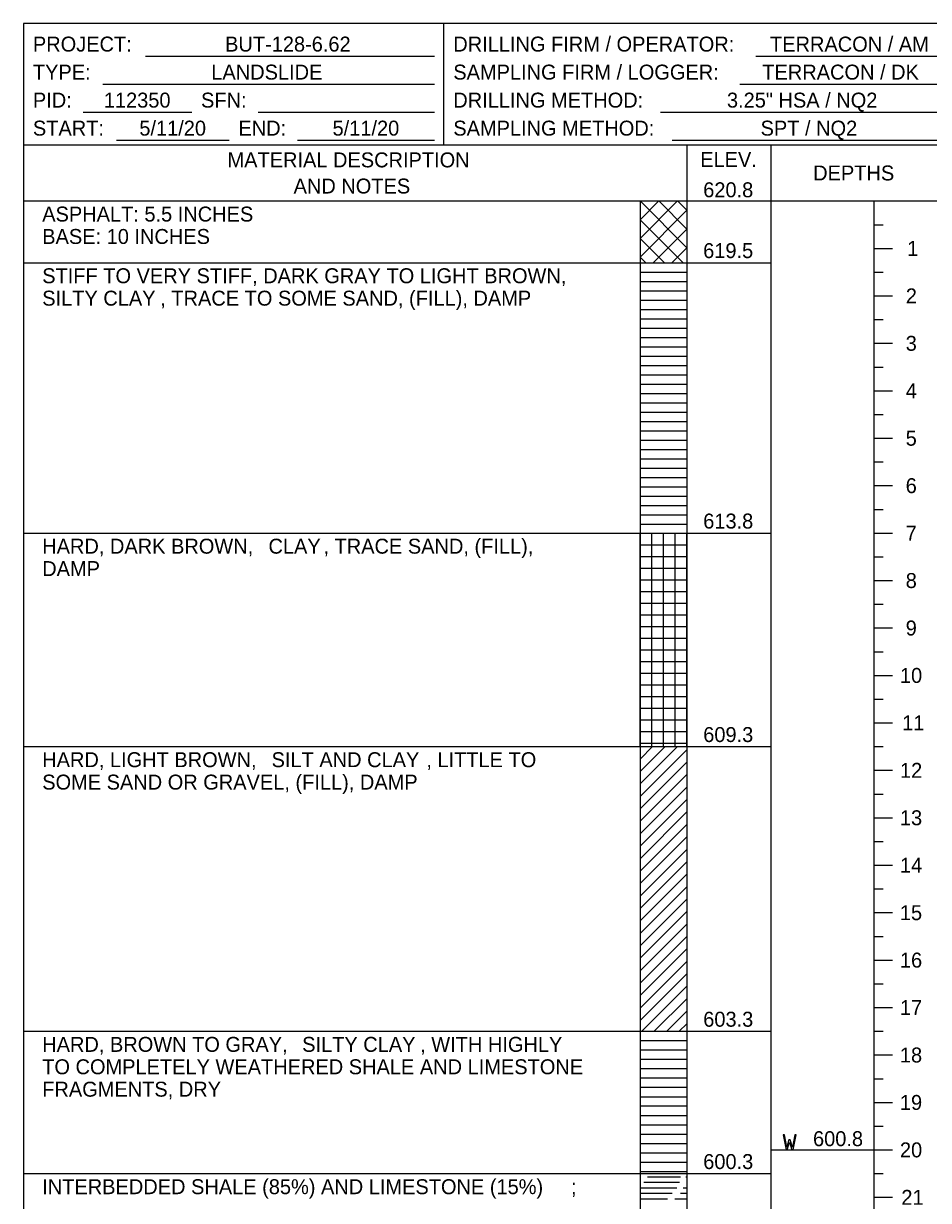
# Model space of a CAD drawing. Extents: x 0 to 0.833, y -0.323 to 0.608.
# Drawn here: x 0 to 0.404, y 0.083 to 0.608 of the extents above; entities that cross this region are included whole.
import ezdxf

# ---------------------------------------------------------------- set-up
doc = ezdxf.new("R2010")
doc.units = 0

# ---------------------------------------------------------------- blocks, each defined once
blk = doc.blocks.new('DGRFC!OHDOT FREE WATER')
blk.add_lwpolyline([(-0.00161, 0), (-0.00102, 0), (0, 0.00346), (0.00102, 0), (0.00161, 0), (0.00292, 0.00667), (0.00233, 0.00667), (0.00126, 0.00118), (0.00029, 0.00444), (-0.00029, 0.00444), (-0.00126, 0.00118), (-0.00233, 0.00667), (-0.00292, 0.00667)], close=True)

msp = doc.modelspace()

# ---------------------------------------------------------------- linework, layer by layer
msp.add_lwpolyline([(0, -0.32328), (0.83333, -0.32328), (0.83333, 0.60833), (0, 0.60833)], close=True)
for points in [[(0.1875, 0.55417), (0.1875, 0.60833)], [(0.05444, 0.59375), (0.18333, 0.59375)], [(0.32667, 0.59375), (0.4125, 0.59375)], [(0.03542, 0.58125), (0.18333, 0.58125)], [(0.31944, 0.58125), (0.4125, 0.58125)], [(0.02653, 0.56875), (0.075, 0.56875)], [(0.10458, 0.56875), (0.18333, 0.56875)], [(0.28403, 0.56875), (0.4125, 0.56875)], [(0, 0.55417), (0.83333, 0.55417)], [(0, 0.55417), (0.83333, 0.55417)], [(0, 0.55417), (0.83333, 0.55417)], [(0, 0.55417), (0.83333, 0.55417)], [(0, 0.55417), (0.83333, 0.55417)], [(0.04153, 0.55625), (0.09167, 0.55625)], [(0.12222, 0.55625), (0.18333, 0.55625)], [(0.2893, 0.55625), (0.4125, 0.55625)], [(0.29583, 0.55417), (0.29583, -0.28575)], [(0.29583, 0.55417), (0.29583, -0.28575)], [(0.33333, 0.55417), (0.33333, -0.28575)], [(0.33333, 0.55417), (0.33333, -0.28575)], [(0, 0.52917), (0.83333, 0.52917)], [(0, 0.52917), (0.83333, 0.52917)], [(0, 0.52917), (0.83333, 0.52917)], [(0, 0.52917), (0.83333, 0.52917)], [(0, 0.52917), (0.83333, 0.52917)], [(0.275, 0.52917), (0.29583, 0.50833)], [(0.275, 0.52083), (0.28333, 0.52917)], [(0.275, 0.5125), (0.29167, 0.52917)], [(0.275, 0.52917), (0.275, 0.50165)], [(0.275, 0.52917), (0.275, -0.28575)], [(0.28333, 0.52917), (0.29583, 0.51667)], [(0.29167, 0.52917), (0.29583, 0.525)], [(0.29583, 0.52917), (0.33333, 0.52917)], [(0.37917, 0.52917), (0.37917, -0.28575)], [(0.275, 0.50417), (0.29583, 0.525)], [(0.275, 0.52083), (0.29418, 0.50165)], [(0.28082, 0.50165), (0.29583, 0.51667)], [(0.37917, 0.51858), (0.38333, 0.51858)], [(0.275, 0.5125), (0.28585, 0.50165)], [(0.275, 0.50417), (0.27752, 0.50165)], [(0.28915, 0.50165), (0.29583, 0.50833)], [(0.37917, 0.508), (0.3875, 0.508)], [(0.37917, 0.508), (0.38333, 0.508)], [(0, 0.50165), (0.275, 0.50165)], [(0.275, 0.50165), (0.29583, 0.50165)], [(0.275, 0.50165), (0.29583, 0.50165)], [(0.275, 0.50165), (0.275, 0.381)], [(0.29583, 0.50165), (0.33333, 0.50165)], [(0.275, 0.49748), (0.29583, 0.49748)], [(0.37917, 0.49742), (0.38333, 0.49742)], [(0.275, 0.49332), (0.29583, 0.49332)], [(0.275, 0.48915), (0.29583, 0.48915)], [(0.275, 0.48498), (0.29583, 0.48498)], [(0.37917, 0.48683), (0.3875, 0.48683)], [(0.37917, 0.48683), (0.38333, 0.48683)], [(0.275, 0.48082), (0.29583, 0.48082)], [(0.275, 0.47665), (0.29583, 0.47665)], [(0.37917, 0.47625), (0.38333, 0.47625)], [(0.275, 0.47248), (0.29583, 0.47248)], [(0.275, 0.46832), (0.29583, 0.46832)], [(0.275, 0.46415), (0.29583, 0.46415)], [(0.37917, 0.46567), (0.3875, 0.46567)], [(0.37917, 0.46567), (0.38333, 0.46567)], [(0.275, 0.45998), (0.29583, 0.45998)], [(0.275, 0.45582), (0.29583, 0.45582)], [(0.275, 0.45165), (0.29583, 0.45165)], [(0.37917, 0.45508), (0.38333, 0.45508)], [(0.275, 0.44748), (0.29583, 0.44748)], [(0.275, 0.44332), (0.29583, 0.44332)], [(0.37917, 0.4445), (0.3875, 0.4445)], [(0.37917, 0.4445), (0.38333, 0.4445)], [(0.275, 0.43915), (0.29583, 0.43915)], [(0.275, 0.43498), (0.29583, 0.43498)], [(0.275, 0.43082), (0.29583, 0.43082)], [(0.37917, 0.43392), (0.38333, 0.43392)], [(0.275, 0.42665), (0.29583, 0.42665)], [(0.275, 0.42248), (0.29583, 0.42248)], [(0.37917, 0.42333), (0.3875, 0.42333)], [(0.37917, 0.42333), (0.38333, 0.42333)], [(0.275, 0.41832), (0.29583, 0.41832)], [(0.275, 0.41415), (0.29583, 0.41415)], [(0.275, 0.40998), (0.29583, 0.40998)], [(0.37917, 0.41275), (0.38333, 0.41275)], [(0.275, 0.40582), (0.29583, 0.40582)], [(0.275, 0.40165), (0.29583, 0.40165)], [(0.37917, 0.40217), (0.3875, 0.40217)], [(0.37917, 0.40217), (0.38333, 0.40217)], [(0.275, 0.39748), (0.29583, 0.39748)], [(0.275, 0.39332), (0.29583, 0.39332)], [(0.275, 0.38915), (0.29583, 0.38915)], [(0.37917, 0.39158), (0.38333, 0.39158)], [(0.275, 0.38498), (0.29583, 0.38498)], [(0, 0.381), (0.275, 0.381)], [(0.275, 0.381), (0.29583, 0.381)], [(0.275, 0.381), (0.29583, 0.381)], [(0.275, 0.28575), (0.275, 0.381)], [(0.275, 0.381), (0.275, 0.28575)], [(0.28021, 0.28575), (0.28021, 0.381)], [(0.28542, 0.28575), (0.28542, 0.381)], [(0.29062, 0.28575), (0.29062, 0.381)], [(0.29583, 0.28575), (0.29583, 0.381)], [(0.29583, 0.381), (0.33333, 0.381)], [(0.37917, 0.381), (0.3875, 0.381)], [(0.37917, 0.381), (0.38333, 0.381)], [(0.275, 0.37579), (0.29583, 0.37579)], [(0.275, 0.37058), (0.29583, 0.37058)], [(0.37917, 0.37042), (0.38333, 0.37042)], [(0.275, 0.36537), (0.29583, 0.36537)], [(0.275, 0.36017), (0.29583, 0.36017)], [(0.37917, 0.35983), (0.3875, 0.35983)], [(0.37917, 0.35983), (0.38333, 0.35983)], [(0.275, 0.35496), (0.29583, 0.35496)], [(0.275, 0.34975), (0.29583, 0.34975)], [(0.37917, 0.34925), (0.38333, 0.34925)], [(0.275, 0.34454), (0.29583, 0.34454)], [(0.275, 0.33933), (0.29583, 0.33933)], [(0.37917, 0.33867), (0.3875, 0.33867)], [(0.37917, 0.33867), (0.38333, 0.33867)], [(0.275, 0.33412), (0.29583, 0.33412)], [(0.275, 0.32892), (0.29583, 0.32892)], [(0.37917, 0.32808), (0.38333, 0.32808)], [(0.275, 0.32371), (0.29583, 0.32371)], [(0.275, 0.3185), (0.29583, 0.3185)], [(0.37917, 0.3175), (0.3875, 0.3175)], [(0.37917, 0.3175), (0.38333, 0.3175)], [(0.275, 0.31329), (0.29583, 0.31329)], [(0.275, 0.30808), (0.29583, 0.30808)], [(0.37917, 0.30692), (0.38333, 0.30692)], [(0.275, 0.30287), (0.29583, 0.30287)], [(0.275, 0.29767), (0.29583, 0.29767)], [(0.37917, 0.29633), (0.3875, 0.29633)], [(0.37917, 0.29633), (0.38333, 0.29633)], [(0.275, 0.29246), (0.29583, 0.29246)], [(0, 0.28575), (0.275, 0.28575)], [(0.275, 0.28725), (0.29583, 0.28725)], [(0.275, 0.28575), (0.29583, 0.28575)], [(0.275, 0.28019), (0.28055, 0.28575)], [(0.275, 0.27464), (0.28611, 0.28575)], [(0.275, 0.26908), (0.29167, 0.28575)], [(0.275, 0.28575), (0.275, 0.15875)], [(0.275, 0.26353), (0.29583, 0.28436)], [(0.29583, 0.28575), (0.33333, 0.28575)], [(0.37917, 0.28575), (0.38333, 0.28575)], [(0.275, 0.25797), (0.29583, 0.2788)], [(0.275, 0.25242), (0.29583, 0.27325)], [(0.37917, 0.27517), (0.3875, 0.27517)], [(0.37917, 0.27517), (0.38333, 0.27517)], [(0.275, 0.24686), (0.29583, 0.26769)], [(0.37917, 0.26458), (0.38333, 0.26458)], [(0.275, 0.24131), (0.29583, 0.26214)], [(0.275, 0.23575), (0.29583, 0.25658)], [(0.37917, 0.254), (0.3875, 0.254)], [(0.37917, 0.254), (0.38333, 0.254)], [(0.275, 0.23019), (0.29583, 0.25103)], [(0.275, 0.22464), (0.29583, 0.24547)], [(0.37917, 0.24342), (0.38333, 0.24342)], [(0.275, 0.21908), (0.29583, 0.23992)], [(0.275, 0.21353), (0.29583, 0.23436)], [(0.37917, 0.23283), (0.3875, 0.23283)], [(0.37917, 0.23283), (0.38333, 0.23283)], [(0.275, 0.20797), (0.29583, 0.22881)], [(0.275, 0.20242), (0.29583, 0.22325)], [(0.37917, 0.22225), (0.38333, 0.22225)], [(0.275, 0.19686), (0.29583, 0.21769)], [(0.275, 0.19131), (0.29583, 0.21214)], [(0.37917, 0.21167), (0.3875, 0.21167)], [(0.37917, 0.21167), (0.38333, 0.21167)], [(0.275, 0.18575), (0.29583, 0.20658)], [(0.275, 0.18019), (0.29583, 0.20103)], [(0.37917, 0.20108), (0.38333, 0.20108)], [(0.275, 0.17464), (0.29583, 0.19547)], [(0.275, 0.16908), (0.29583, 0.18992)], [(0.37917, 0.1905), (0.3875, 0.1905)], [(0.37917, 0.1905), (0.38333, 0.1905)], [(0.275, 0.16353), (0.29583, 0.18436)], [(0.27578, 0.15875), (0.29583, 0.17881)], [(0.37917, 0.17992), (0.38333, 0.17992)], [(0.28133, 0.15875), (0.29583, 0.17325)], [(0.37917, 0.16933), (0.3875, 0.16933)], [(0.37917, 0.16933), (0.38333, 0.16933)], [(0.28689, 0.15875), (0.29583, 0.16769)], [(0, 0.15875), (0.275, 0.15875)], [(0.275, 0.15875), (0.29583, 0.15875)], [(0.275, 0.15875), (0.29583, 0.15875)], [(0.275, 0.15875), (0.275, 0.09525)], [(0.29244, 0.15875), (0.29583, 0.16214)], [(0.29583, 0.15875), (0.33333, 0.15875)], [(0.37917, 0.15875), (0.38333, 0.15875)], [(0.275, 0.15458), (0.29583, 0.15458)], [(0.275, 0.15042), (0.29583, 0.15042)], [(0.37917, 0.14817), (0.3875, 0.14817)], [(0.37917, 0.14817), (0.38333, 0.14817)], [(0.275, 0.14625), (0.29583, 0.14625)], [(0.275, 0.14208), (0.29583, 0.14208)], [(0.275, 0.13792), (0.29583, 0.13792)], [(0.37917, 0.13758), (0.38333, 0.13758)], [(0.275, 0.13375), (0.29583, 0.13375)], [(0.275, 0.12958), (0.29583, 0.12958)], [(0.37917, 0.127), (0.3875, 0.127)], [(0.37917, 0.127), (0.38333, 0.127)], [(0.275, 0.12542), (0.29583, 0.12542)], [(0.275, 0.12125), (0.29583, 0.12125)], [(0.275, 0.11708), (0.29583, 0.11708)], [(0.37917, 0.11642), (0.38333, 0.11642)], [(0.275, 0.11292), (0.29583, 0.11292)], [(0.275, 0.10875), (0.29583, 0.10875)], [(0.33333, 0.10583), (0.37917, 0.10583)], [(0.37917, 0.10583), (0.3875, 0.10583)], [(0.37917, 0.10583), (0.38333, 0.10583)], [(0.275, 0.10458), (0.29583, 0.10458)], [(0.275, 0.10042), (0.29583, 0.10042)], [(0, 0.09525), (0.275, 0.09525)], [(0.275, 0.09625), (0.29583, 0.09625)], [(0.275, 0.09525), (0.29583, 0.09525)], [(0.275, 0.09525), (0.29583, 0.09525)], [(0.275, 0.09525), (0.275, -0.28575)], [(0.29583, 0.09525), (0.33333, 0.09525)], [(0.37917, 0.09525), (0.38333, 0.09525)], [(0.27667, 0.09142), (0.29258, 0.09142)], [(0.27825, 0.09383), (0.293, 0.09383)], [(0.29542, 0.09383), (0.29583, 0.09383)], [(0.275, 0.08892), (0.29133, 0.08892)], [(0.275, 0.0865), (0.28933, 0.0865)], [(0.293, 0.0865), (0.29583, 0.0865)], [(0.29417, 0.08892), (0.29583, 0.08892)], [(0.37917, 0.08467), (0.3875, 0.08467)], [(0.37917, 0.08467), (0.38333, 0.08467)], [(0.275, 0.084), (0.28725, 0.084)], [(0.2905, 0.084), (0.29583, 0.084)]]:
    msp.add_lwpolyline(points)

# ---------------------------------------------------------------- block references
msp.add_blockref('DGRFC!OHDOT FREE WATER', (0.34167, 0.10583))

# ---------------------------------------------------------------- texts
for s, height, p in [('PROJECT:', 0.006667, (0.00417, 0.59583)), ('BUT-128-6.62', 0.0066667, (0.08989, 0.59583)), ('DRILLING FIRM / OPERATOR:', 0.0066667, (0.19167, 0.59583)), ('TERRACON / AM', 0.0066667, (0.33293, 0.59583)), ('TYPE:', 0.006667, (0.00417, 0.58333)), ('LANDSLIDE', 0.006667, (0.08374, 0.58333)), ('SAMPLING FIRM / LOGGER:', 0.0066667, (0.19167, 0.58333)), ('TERRACON / DK', 0.0066667, (0.32949, 0.58333)), ('112350', 0.006667, (0.0358, 0.57083)), ('SFN:', 0.006667, (0.07917, 0.57083)), ('DRILLING METHOD:', 0.0066667, (0.19167, 0.57083)), ('3.25" HSA / NQ2', 0.0066667, (0.31373, 0.57083)), ('PID:', 0.006667, (0.00417, 0.57083)), ('START:', 0.006667, (0.00417, 0.55833)), ('5/11/20', 0.006667, (0.05164, 0.55833)), ('END:', 0.006667, (0.09583, 0.55833)), ('5/11/20', 0.006667, (0.13782, 0.55833)), ('SAMPLING METHOD:', 0.0066667, (0.19167, 0.55833)), ('SPT / NQ2', 0.006667, (0.32872, 0.55833)), ('MATERIAL DESCRIPTION', 0.0066667, (0.09097, 0.54417)), ('ELEV.', 0.006667, (0.30179, 0.54437)), ('DEPTHS', 0.006667, (0.35218, 0.53833)), ('AND NOTES', 0.006667, (0.12044, 0.5325)), ('620.8', 0.006667, (0.30314, 0.53083)), ('ASPHALT: 5.5 INCHES', 0.0066667, (0.00833, 0.52)), ('BASE: 10 INCHES', 0.0066667, (0.00833, 0.51)), ('619.5', 0.006667, (0.30312, 0.50369)), ('1', 0.00667, (0.3941, 0.50467)), ('STIFF TO VERY STIFF, DARK GRAY TO LIGHT BROWN,', 0.0066667, (0.00833, 0.49248)), ('SILTY CLAY', 0.006667, (0.00833, 0.48248)), (', TRACE TO SOME SAND, (FILL), DAMP', 0.0066667, (0.06097, 0.48248)), ('2', 0.00667, (0.39349, 0.4835)), ('3', 0.00667, (0.39345, 0.46233)), ('4', 0.00667, (0.39347, 0.44117)), ('5', 0.00667, (0.39343, 0.42)), ('6', 0.00667, (0.39345, 0.39883)), ('613.8', 0.006667, (0.30314, 0.38304)), ('7', 0.00667, (0.39345, 0.37767)), ('HARD, DARK BROWN, ', 0.0066667, (0.00833, 0.37183)), ('CLAY', 0.006667, (0.10925, 0.37183)), (', TRACE SAND, (FILL),', 0.0066667, (0.13376, 0.37183)), ('DAMP', 0.006667, (0.00833, 0.36183)), ('8', 0.00667, (0.39345, 0.3565)), ('9', 0.00667, (0.39345, 0.33533)), ('10', 0.006667, (0.39088, 0.31417)), ('11', 0.006667, (0.39186, 0.293)), ('609.3', 0.006667, (0.30314, 0.28779)), ('HARD, LIGHT BROWN, ', 0.0066667, (0.00833, 0.27658)), ('SILT AND CLAY', 0.0066667, (0.11063, 0.27658)), (', LITTLE TO', 0.0066667, (0.17964, 0.27658)), ('12', 0.006667, (0.3909, 0.27183)), ('SOME SAND OR GRAVEL, (FILL), DAMP', 0.0066667, (0.00833, 0.26658)), ('13', 0.006667, (0.39087, 0.25067)), ('14', 0.006667, (0.39088, 0.2295)), ('15', 0.006667, (0.39084, 0.20833)), ('16', 0.006667, (0.39087, 0.18717)), ('17', 0.006667, (0.39087, 0.166)), ('603.3', 0.006667, (0.30314, 0.16079)), ('HARD, BROWN TO GRAY, ', 0.0066667, (0.00833, 0.14958)), ('SILTY CLAY', 0.006667, (0.12427, 0.14958)), (', WITH HIGHLY', 0.0066667, (0.1769, 0.14958)), ('18', 0.006667, (0.39086, 0.14483)), ('TO COMPLETELY WEATHERED SHALE AND LIMESTONE', 0.0066667, (0.00833, 0.13958)), ('FRAGMENTS, DRY', 0.0066667, (0.00833, 0.12958)), ('19', 0.006667, (0.39086, 0.12367)), ('600.8', 0.006667, (0.35211, 0.1075)), ('20', 0.006667, (0.39088, 0.1025)), ('600.3', 0.006667, (0.30314, 0.09729)), ('INTERBEDDED SHALE (85%) AND LIMESTONE (15%)', 0.0066667, (0.00833, 0.08608)), (';', 0.00667, (0.24416, 0.08608)), ('21', 0.006667, (0.39151, 0.08133))]:
    msp.add_text(s, height=height).set_placement(p)

doc.saveas('drawing.dxf')
